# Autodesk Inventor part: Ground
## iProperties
Created: 2006-02
Part Number: Ground
Document SubType Name: Modeling
Designer: FranzK
Mass: 1.1625e+07 g
Surface Area: 1.60325e+06 cm^2
Volume: 1.1625e+07 cm^3
Density: 1 g/cm^3
CSToolsMass: 11625.0
CSToolsVolume: 11625000000.0
CSToolsArea: 1603250.0
Author: FranzK
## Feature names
1. Extrusion1
